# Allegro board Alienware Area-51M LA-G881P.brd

Outline 398.4 x 200.1 mm; copper layers: TOP, GND1, IN1, GND2, IN2, IN3, GND3, IN4, GND4, BOTTOM. Coordinates in mm from the lower left corner of the outline.

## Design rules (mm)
constraint set DEFAULT: min track width 0.112
net group 10: nets HDA_BIT_CLK_R MIC_CLK
net group CLK_PEG_0: nets CLK_PEG_N0 CLK_PEG_P0
net group CORE_V1: nets CORE_V1N CORE_V1P
net group CORE_V2: nets CORE_V2N CORE_V2P
net group CORE_V3: nets CORE_V3N CORE_V3P
net group CORE_V4: nets CORE_V4N CORE_V4P
net group CORE_V5: nets CORE_V5N CORE_V5P
net group CORE_V6: nets CORE_V6N CORE_V6P
net group CPU-SIGNAL: nets EC_PECI H_PM_SYNC
net group CSI_CHG: nets CSIN_CHG CSIP_CHG
net group CSI_ISL95338_1: nets CSIN_ISL95338_1 CSIP_ISL95338_1
net group CSI_ISL95338_2: nets CSIN_ISL95338_2 CSIP_ISL95338_2
net group CSO_CHG: nets CSON_CHG CSOP_CHG
net group CSS_1: nets CSSN_1 CSSP_1
net group CSS_2: nets CSSN_2 CSSP_2
net group DDR_B_CLK2: nets DDR_B_CLK2 DDR_B_CLK#2
net group DDR_B_CLK3: nets DDR_B_CLK3 DDR_B_CLK#3
net group DIFFPAIR22: nets TP_CLK_R TP_DATA_R
net group DIFFPAIR23: nets TP_CLK TP_DATA
net group DIFFPAIR40: nets PCIE_CTX_TRX_N24 PCIE_CTX_TRX_P24
net group DIFFPAIR41: nets PCIE_CTX_TRX_N23 PCIE_CTX_TRX_P23
net group DIFFPAIR42: nets PCIE_CTX_TRX_N22 PCIE_CTX_TRX_P22
net group DIFFPAIR43: nets PCIE_CTX_TRX_N21 PCIE_CTX_TRX_P21
net group DIFFPAIR44: nets PCIE_CRX_TTX_N24 PCIE_CRX_TTX_P24
net group DIFFPAIR45: nets PCIE_CRX_TTX_N23 PCIE_CRX_TTX_P23
net group DIFFPAIR46: nets PCIE_CRX_TTX_N22 PCIE_CRX_TTX_P22
net group DIFFPAIR47: nets PCIE_CRX_TTX_N21 PCIE_CRX_TTX_P21
net group DIFFPAIR48: nets USB20_N10_R USB20_P10_R
net group GT_V1: nets GT_V1N GT_V1P
net group GT_V2: nets GT_V2N GT_V2P
net group ISEN1_CHG: nets ISEN1N_CHG ISEN1P_CHG
net group ISUM_GT: nets ISUMN_GT ISUMP_GT
net group ISUM_VCORE: nets ISUMN_VCORE ISUMP_VCORE
net group PCH_SMB: nets PCH_SMBCLK PCH_SMBDATA
net group PCH_XDP_CLK_: nets PCH_XDP_CLK_N PCH_XDP_CLK_P
net group PCIE_CTX_C_RD_TRX_24: nets PCIE_CTX_C_RD_TRX_N24 PCIE_CTX_C_RD_TRX_P24
net group PCIE_CTX_C_TRX_22: nets PCIE_CTX_C_TRX_N22 PCIE_CTX_C_TRX_P22
net group PCIE_CTX_C_TRX_23: nets PCIE_CTX_C_TRX_N23 PCIE_CTX_C_TRX_P23
net group PCIE_CTX_C_TRX_24: nets PCIE_CTX_C_TRX_N24 PCIE_CTX_C_TRX_P24
net group PCIE_RCOMP: nets PCIE_RCOMPN PCIE_RCOMPP
net group REMOTE1: nets REMOTE1+ REMOTE1-
net group REMOTE2: nets REMOTE2+ REMOTE2-
net group REMOTE3: nets REMOTE3+ REMOTE3-
net group REMOTE4: nets REMOTE4+ REMOTE4-
net group SENSE: nets VCCIO_SENSE VCCSA_SENSE
net group TBTA_DIG_AUD_: nets TBTA_DIG_AUD_N TBTA_DIG_AUD_P
net group UART: nets UART_2_PRXD_DTXD UART_2_PTXD_DRXD
net group VCCSA_SENSE: nets VCCSA_SENSEN VCCSA_SENSEP
net group 85H_PCIE: nets CNV_PRX_DTX_N0
net group ASYNCHRONOUS: nets CALDERA_RST# CDRA_RST# CPU_TRIGGER DGPU_HOLD_RST# DGPU_PWROK EDP_RCOMP H_CPUPWRGD H_DRAMRST# H_PECI H_PM_DOWN H_PM_SYNC_R H_PROCHOT# H_PROCHOT#_R H_THERMTRIP# H_THERMTRIP#_R H_VCCST_PWRGD PCH_DPWROK PCH_PLTRST# PCH_PWROK PCH_TRIGGER PEG_RCOMP SYS_PWROK TBT_RST#_R USB2_COMP VR_SVID_CLK
net group AUDIO: nets HDA_BIT_CLK HDA_RST# HDA_SDIN HDA_SDOUT HDA_SDOUT_R HDA_SYNC HDA_SYNC_R
net group CNV_PRX_DTX_0_R: nets CNV_PRX_DTX_N0_R
net group CRYSTAL: nets PCH_RTCX1 PCH_RTCX2 TBT_XTAL_25_IN TBT_XTAL_25_OUT XTAL24_IN XTAL24_IN_R XTAL24_OUT XTAL24_OUT_R
net group DDI: nets CPU_DP1_AUXN CPU_DP1_AUXN_C CPU_DP1_AUXP CPU_DP1_AUXP_C CPU_DP1_HPD CPU_DP1_N0 CPU_DP1_N0_C CPU_DP1_N1 CPU_DP1_N1_C CPU_DP1_N2 CPU_DP1_N2_C CPU_DP1_N3 CPU_DP1_N3_C CPU_DP1_P0 CPU_DP1_P0_C CPU_DP1_P1 CPU_DP1_P1_C CPU_DP1_P2 CPU_DP1_P2_C CPU_DP1_P3 CPU_DP1_P3_C CPU_DP2_AUXN CPU_DP2_AUXN_C CPU_DP2_AUXP CPU_DP2_AUXP_C CPU_DP2_HPD CPU_DP2_N0 CPU_DP2_N0_C CPU_DP2_N1 CPU_DP2_N1_C CPU_DP2_N2 CPU_DP2_N2_C CPU_DP2_N3 CPU_DP2_N3_C CPU_DP2_P0 CPU_DP2_P0_C CPU_DP2_P1 CPU_DP2_P1_C CPU_DP2_P2 CPU_DP2_P2_C CPU_DP2_P3 CPU_DP2_P3_C
net group DDRA-ADD: nets DDR_A_ACT# DDR_A_BA0 DDR_A_BA1 DDR_A_BG0 DDR_A_BG1 DDR_A_CAS# DDR_A_MA0 DDR_A_MA1 DDR_A_MA2 DDR_A_MA3 DDR_A_MA4 DDR_A_MA5 DDR_A_MA6 DDR_A_MA7 DDR_A_MA8 DDR_A_MA9 DDR_A_MA10 DDR_A_MA11 DDR_A_MA12 DDR_A_MA13 DDR_A_PAR DDR_A_RAS# DDR_A_WE#
net group DDRA-CLK: nets DDR_A_CLK0 DDR_A_CLK1 DDR_A_CLK2 DDR_A_CLK3 DDR_A_CLK#0 DDR_A_CLK#1 DDR_A_CLK#2 DDR_A_CLK#3
net group DDRA-CTL: nets DDR_A_CKE0 DDR_A_CKE1 DDR_A_CKE2 DDR_A_CKE3 DDR_A_CS#0 DDR_A_CS#1 DDR_A_CS#2 DDR_A_CS#3 DDR_A_ODT0 DDR_A_ODT1 DDR_A_ODT2 DDR_A_ODT3
net group DDRA-D0: nets DDR_A_D0 DDR_A_D1 DDR_A_D2 DDR_A_D3 DDR_A_D4 DDR_A_D5 DDR_A_D6 DDR_A_D7
net group DDRA-D1: nets DDR_A_D8 DDR_A_D9 DDR_A_D10 DDR_A_D11 DDR_A_D12 DDR_A_D13 DDR_A_D14 DDR_A_D15
net group DDRA-D2: nets DDR_A_D16 DDR_A_D17 DDR_A_D18 DDR_A_D19 DDR_A_D20 DDR_A_D21 DDR_A_D22 DDR_A_D23
net group DDRA-D3: nets DDR_A_D24 DDR_A_D25 DDR_A_D26 DDR_A_D27 DDR_A_D28 DDR_A_D29 DDR_A_D30 DDR_A_D31
net group DDRA-D4: nets DDR_A_D32 DDR_A_D33 DDR_A_D34 DDR_A_D35 DDR_A_D36 DDR_A_D37 DDR_A_D38 DDR_A_D39
net group DDRA-D5: nets DDR_A_D40 DDR_A_D41 DDR_A_D42 DDR_A_D43 DDR_A_D44 DDR_A_D45 DDR_A_D46 DDR_A_D47
net group DDRA-D6: nets DDR_A_D48 DDR_A_D49 DDR_A_D50 DDR_A_D51 DDR_A_D52 DDR_A_D53 DDR_A_D54 DDR_A_D55
net group DDRA-D7: nets DDR_A_D56 DDR_A_D57 DDR_A_D58 DDR_A_D59 DDR_A_D60 DDR_A_D61 DDR_A_D62 DDR_A_D63
net group DDRA-DQS: nets DDR_A_DQS0 DDR_A_DQS1 DDR_A_DQS2 DDR_A_DQS3 DDR_A_DQS4 DDR_A_DQS5 DDR_A_DQS6 DDR_A_DQS7 DDR_A_DQS#0 DDR_A_DQS#1 DDR_A_DQS#2 DDR_A_DQS#3 DDR_A_DQS#4 DDR_A_DQS#5 DDR_A_DQS#6 DDR_A_DQS#7
net group DDRA-MA: nets DDR_A_ALERT#
net group DDRA-RESET: nets DDR_A_DRAMRST#
net group DDRB-ADD: nets DDR_B_ACT# DDR_B_BA0 DDR_B_BA1 DDR_B_BG0 DDR_B_BG1 DDR_B_CAS# DDR_B_MA0 DDR_B_MA1 DDR_B_MA2 DDR_B_MA3 DDR_B_MA4 DDR_B_MA5 DDR_B_MA6 DDR_B_MA7 DDR_B_MA8 DDR_B_MA9 DDR_B_MA10 DDR_B_MA11 DDR_B_MA12 DDR_B_MA13 DDR_B_PAR DDR_B_RAS# DDR_B_WE#
net group DDRB-CLK: nets DDR_B_CLK0 DDR_B_CLK1 DDR_B_CLK#0 DDR_B_CLK#1
net group DDRB-CTL: nets DDR_B_CKE0 DDR_B_CKE1 DDR_B_CKE2 DDR_B_CKE3 DDR_B_CS#0 DDR_B_CS#1 DDR_B_CS#2 DDR_B_CS#3 DDR_B_ODT0 DDR_B_ODT1 DDR_B_ODT2 DDR_B_ODT3
net group DDRB-D0: nets DDR_B_D0 DDR_B_D1 DDR_B_D2 DDR_B_D3 DDR_B_D4 DDR_B_D5 DDR_B_D6 DDR_B_D7
net group DDRB-D1: nets DDR_B_D8 DDR_B_D9 DDR_B_D10 DDR_B_D11 DDR_B_D12 DDR_B_D13 DDR_B_D14 DDR_B_D15
net group DDRB-D2: nets DDR_B_D16 DDR_B_D17 DDR_B_D18 DDR_B_D19 DDR_B_D20 DDR_B_D21 DDR_B_D22 DDR_B_D23
net group DDRB-D3: nets DDR_B_D24 DDR_B_D25 DDR_B_D26 DDR_B_D27 DDR_B_D28 DDR_B_D29 DDR_B_D30 DDR_B_D31
net group DDRB-D4: nets DDR_B_D32 DDR_B_D33 DDR_B_D34 DDR_B_D35 DDR_B_D36 DDR_B_D37 DDR_B_D38 DDR_B_D39
net group DDRB-D5: nets DDR_B_D40 DDR_B_D41 DDR_B_D42 DDR_B_D43 DDR_B_D44 DDR_B_D45 DDR_B_D46 DDR_B_D47
net group DDRB-D6: nets DDR_B_D48 DDR_B_D49 DDR_B_D50 DDR_B_D51 DDR_B_D52 DDR_B_D53 DDR_B_D54 DDR_B_D55
net group DDRB-D7: nets DDR_B_D56 DDR_B_D57 DDR_B_D58 DDR_B_D59 DDR_B_D60 DDR_B_D61 DDR_B_D62 DDR_B_D63
net group DDRB-DQS: nets DDR_B_DQS0 DDR_B_DQS1 DDR_B_DQS2 DDR_B_DQS3 DDR_B_DQS4 DDR_B_DQS5 DDR_B_DQS6 DDR_B_DQS7 DDR_B_DQS#0 DDR_B_DQS#1 DDR_B_DQS#2 DDR_B_DQS#3 DDR_B_DQS#4 DDR_B_DQS#5 DDR_B_DQS#6 DDR_B_DQS#7
net group DDRB-MA: nets DDR_B_ALERT#
net group DDRB-RESET: nets DDR_B_DRAMRST#
net group DIFFPAIR2: nets DAT_SMB
net group DMI: nets DMI_CRX_PTX_N0 DMI_CRX_PTX_N1 DMI_CRX_PTX_N2 DMI_CRX_PTX_N3 DMI_CRX_PTX_P0 DMI_CRX_PTX_P1 DMI_CRX_PTX_P2 DMI_CRX_PTX_P3 DMI_CTX_PRX_N0 DMI_CTX_PRX_N1 DMI_CTX_PRX_N2 DMI_CTX_PRX_N3 DMI_CTX_PRX_P0 DMI_CTX_PRX_P1 DMI_CTX_PRX_P2 DMI_CTX_PRX_P3
net group EMI: nets BST1_R_ISL95338_1 BST1_R_ISL95338_2 BST2_3V BST2_5V BST2_+1VALWP BST2_R_ISL95338_1 BST2_R_ISL95338_2 BST2_VCCIO BST_1.2V BST_3V BST_5V BST_+1VALWP BST_CHG BST_CHG_R BST_VCCIO CKXTAL1 CKXTAL1_R CKXTAL2 CKXTAL2_R CLK_PCI_ESPI CLK_SMB CNV_BRI_PRX_DTX CNV_BRI_PRX_DTX_R CNV_BRI_PTX_DRX CNV_BRI_PTX_DRX_R CNV_WT_RCOMP CPU_DISPA_BCLK CPU_DISPA_BCLK_R DDR_VTT_CNTL DP_HPD_PCH EC_PECI_R EC_RX EC_TX HDA_SPKR HDMI_HPD_PCH LG1_ISL95338_1 LG1_ISL95338_2 LG2_ISL95338_1 LG2_ISL95338_2 LG_3V LG_5V LX2_ISL95338_1 LX_3V LX_5V LX_VCCIO OSC24M_IN OSC24M_IN_R OSC24M_OUT OSC24M_OUT_R PCH_DP3_CTRL_DATA REFCLK_CNV REFCLK_CNV_H REFCLK_CNV_R RJ45_CT RJ45_CT0 RJ45_CT1 RJ45_CT2 RJ45_CT3 SNB_3V SNB_5V SNB_VCCIO SPI_CLK_R SUSCLK TBT_EE_CLK_R TBT_TMU_CLK_OUT TBTA_HPD TBTA_LSRX TBTA_LSTX UG1_ISL95338_2 UG2_ISL95338_1 UG2_ISL95338_2 UG_3V UG_5V UG_CHG UG_CHG_R VR_SVID_CLK_R
net group I2C: nets I2C_0_SCL I2C_0_SCL_R I2C_0_SDA I2C_0_SDA_R ISH_I2C0_SCL ISH_I2C0_SDA ISH_I2C1_SCL ISH_I2C1_SCL_R ISH_I2C1_SDA ISH_I2C1_SDA_R TBT_I2C_SCL TBT_I2C_SDA
net group LAN: nets LAN_MDIN0 LAN_MDIN1 LAN_MDIN2 LAN_MDIN3 LAN_MDIP0 LAN_MDIP1 LAN_MDIP2 LAN_MDIP3 RJ45_MDIN0 RJ45_MDIN1 RJ45_MDIN2 RJ45_MDIN3 RJ45_MDIP0 RJ45_MDIP1 RJ45_MDIP2 RJ45_MDIP3
net group PCIE: nets CNV_PRX_DTX_N1 CNV_PRX_DTX_N1_R CNV_PRX_DTX_P0 CNV_PRX_DTX_P0_R CNV_PRX_DTX_P1 CNV_PRX_DTX_P1_R CNV_PTX_C_DRX_N0 CNV_PTX_C_DRX_N1 CNV_PTX_C_DRX_P0 CNV_PTX_C_DRX_P1 CNV_PTX_DRX_N0 CNV_PTX_DRX_N1 CNV_PTX_DRX_P0 CNV_PTX_DRX_P1 CNV_RGI_PRX_DTX CNV_RGI_PRX_DTX_R CNV_RGI_PTX_DRX CNV_RGI_PTX_DRX_R PCIE_CRX_C_RD_TTX_N21 PCIE_CRX_C_RD_TTX_N22 PCIE_CRX_C_RD_TTX_N23 PCIE_CRX_C_RD_TTX_N24 PCIE_CRX_C_RD_TTX_P21 PCIE_CRX_C_RD_TTX_P22 PCIE_CRX_C_RD_TTX_P23 PCIE_CRX_C_RD_TTX_P24 PCIE_CRX_C_TTX_N21 PCIE_CRX_C_TTX_N22 PCIE_CRX_C_TTX_N23 PCIE_CRX_C_TTX_N24 PCIE_CRX_C_TTX_P21 PCIE_CRX_C_TTX_P22 PCIE_CRX_C_TTX_P23 PCIE_CRX_C_TTX_P24 PCIE_CRX_RD_TTX_N21 PCIE_CRX_RD_TTX_N22 PCIE_CRX_RD_TTX_N23 PCIE_CRX_RD_TTX_N24 PCIE_CRX_RD_TTX_P21 PCIE_CRX_RD_TTX_P22 PCIE_CRX_RD_TTX_P23 PCIE_CRX_RD_TTX_P24 PCIE_CTX_C_RD_TRX_N21 PCIE_CTX_C_RD_TRX_N22 PCIE_CTX_C_RD_TRX_N23 PCIE_CTX_C_RD_TRX_P21 PCIE_CTX_C_RD_TRX_P22 PCIE_CTX_C_RD_TRX_P23 PCIE_CTX_C_TRX_N21 PCIE_CTX_C_TRX_P21 PCIE_CTX_RD_TRX_N21 PCIE_CTX_RD_TRX_N22 PCIE_CTX_RD_TRX_N23 PCIE_CTX_RD_TRX_N24 PCIE_CTX_RD_TRX_P21 PCIE_CTX_RD_TRX_P22 PCIE_CTX_RD_TRX_P23 PCIE_CTX_RD_TRX_P24 PCIE_PRX_C_DTX_N15 PCIE_PRX_C_DTX_P15 PCIE_PRX_DTX_N9 PCIE_PRX_DTX_N10 PCIE_PRX_DTX_N11 PCIE_PRX_DTX_N12 PCIE_PRX_DTX_N15 PCIE_PRX_DTX_N16 PCIE_PRX_DTX_N17 PCIE_PRX_DTX_N18 PCIE_PRX_DTX_N19 PCIE_PRX_DTX_N20 PCIE_PRX_DTX_P9 PCIE_PRX_DTX_P10 PCIE_PRX_DTX_P11 PCIE_PRX_DTX_P12 PCIE_PRX_DTX_P15 PCIE_PRX_DTX_P16 PCIE_PRX_DTX_P17 PCIE_PRX_DTX_P18 PCIE_PRX_DTX_P19 PCIE_PRX_DTX_P20 PCIE_PTX_C_DRX_N9 PCIE_PTX_C_DRX_N10 PCIE_PTX_C_DRX_N11 PCIE_PTX_C_DRX_N12 PCIE_PTX_C_DRX_N15 PCIE_PTX_C_DRX_N16 PCIE_PTX_C_DRX_N17 PCIE_PTX_C_DRX_N18 PCIE_PTX_C_DRX_N19 PCIE_PTX_C_DRX_N20 PCIE_PTX_C_DRX_P9 PCIE_PTX_C_DRX_P10 PCIE_PTX_C_DRX_P11 PCIE_PTX_C_DRX_P12 PCIE_PTX_C_DRX_P15 PCIE_PTX_C_DRX_P16 PCIE_PTX_C_DRX_P17 PCIE_PTX_C_DRX_P18 PCIE_PTX_C_DRX_P19 PCIE_PTX_C_DRX_P20 PCIE_PTX_DRX_N9 PCIE_PTX_DRX_N10 PCIE_PTX_DRX_N11 PCIE_PTX_DRX_N12 PCIE_PTX_DRX_N15 PCIE_PTX_DRX_N16 PCIE_PTX_DRX_N17 PCIE_PTX_DRX_N18 PCIE_PTX_DRX_N19 PCIE_PTX_DRX_N20 PCIE_PTX_DRX_P9 PCIE_PTX_DRX_P10 PCIE_PTX_DRX_P11 PCIE_PTX_DRX_P12 PCIE_PTX_DRX_P15 PCIE_PTX_DRX_P16 PCIE_PTX_DRX_P17 PCIE_PTX_DRX_P18 PCIE_PTX_DRX_P19 PCIE_PTX_DRX_P20
net group PEG: nets PEG_CRX_C_GTX_N0 PEG_CRX_C_GTX_N1 PEG_CRX_C_GTX_N2 PEG_CRX_C_GTX_N3 PEG_CRX_C_GTX_N4 PEG_CRX_C_GTX_N5 PEG_CRX_C_GTX_N6 PEG_CRX_C_GTX_N7 PEG_CRX_C_GTX_P0 PEG_CRX_C_GTX_P1 PEG_CRX_C_GTX_P2 PEG_CRX_C_GTX_P3 PEG_CRX_C_GTX_P4 PEG_CRX_C_GTX_P5 PEG_CRX_C_GTX_P6 PEG_CRX_C_GTX_P7 PEG_CRX_C_RD_GTX_N8 PEG_CRX_C_RD_GTX_N9 PEG_CRX_C_RD_GTX_N10 PEG_CRX_C_RD_GTX_N11 PEG_CRX_C_RD_GTX_P8 PEG_CRX_C_RD_GTX_P9 PEG_CRX_C_RD_GTX_P10 PEG_CRX_C_RD_GTX_P11 PEG_CRX_GTX_N0 PEG_CRX_GTX_N1 PEG_CRX_GTX_N2 PEG_CRX_GTX_N3 PEG_CRX_GTX_N4 PEG_CRX_GTX_N5 PEG_CRX_GTX_N6 PEG_CRX_GTX_N7 PEG_CRX_GTX_N8 PEG_CRX_GTX_N9 PEG_CRX_GTX_N10 PEG_CRX_GTX_N11 PEG_CRX_GTX_P0 PEG_CRX_GTX_P1 PEG_CRX_GTX_P2 PEG_CRX_GTX_P3 PEG_CRX_GTX_P4 PEG_CRX_GTX_P5 PEG_CRX_GTX_P6 PEG_CRX_GTX_P7 PEG_CRX_GTX_P8 PEG_CRX_GTX_P9 PEG_CRX_GTX_P10 PEG_CRX_GTX_P11 PEG_CRX_RD_GTX_N8 PEG_CRX_RD_GTX_N9 PEG_CRX_RD_GTX_N10 PEG_CRX_RD_GTX_N11 PEG_CRX_RD_GTX_P8 PEG_CRX_RD_GTX_P9 PEG_CRX_RD_GTX_P10 PEG_CRX_RD_GTX_P11 PEG_CTX_C_GRX_N0 PEG_CTX_C_GRX_N1 PEG_CTX_C_GRX_N2 PEG_CTX_C_GRX_N3 PEG_CTX_C_GRX_N4 PEG_CTX_C_GRX_N5 PEG_CTX_C_GRX_N6 PEG_CTX_C_GRX_N7 PEG_CTX_C_GRX_N8 PEG_CTX_C_GRX_N9 PEG_CTX_C_GRX_N10 PEG_CTX_C_GRX_N11 PEG_CTX_C_GRX_P0 PEG_CTX_C_GRX_P1 PEG_CTX_C_GRX_P2 PEG_CTX_C_GRX_P3 PEG_CTX_C_GRX_P4 PEG_CTX_C_GRX_P5 PEG_CTX_C_GRX_P6 PEG_CTX_C_GRX_P7 PEG_CTX_C_GRX_P8 PEG_CTX_C_GRX_P9 PEG_CTX_C_GRX_P10 PEG_CTX_C_GRX_P11 PEG_CTX_GRX_N0 PEG_CTX_GRX_N1 PEG_CTX_GRX_N2 PEG_CTX_GRX_N3 PEG_CTX_GRX_N4 PEG_CTX_GRX_N5 PEG_CTX_GRX_N6 PEG_CTX_GRX_N7 PEG_CTX_GRX_N8 PEG_CTX_GRX_N9 PEG_CTX_GRX_N10 PEG_CTX_GRX_N11 PEG_CTX_GRX_P0 PEG_CTX_GRX_P1 PEG_CTX_GRX_P2 PEG_CTX_GRX_P3 PEG_CTX_GRX_P4 PEG_CTX_GRX_P5 PEG_CTX_GRX_P6 PEG_CTX_GRX_P7 PEG_CTX_GRX_P8 PEG_CTX_GRX_P9 PEG_CTX_GRX_P10 PEG_CTX_GRX_P11
net group PLATFORM-CLK: nets CLK_CNV_PRX_DTX_N CLK_CNV_PRX_DTX_N_R CLK_CNV_PRX_DTX_P CLK_CNV_PRX_DTX_P_R CLK_CNV_PTX_DRX_N CLK_CNV_PTX_DRX_N_R CLK_CNV_PTX_DRX_P CLK_CNV_PTX_DRX_P_R CLK_PCIE_DGPU#_C CLK_PCIE_DGPU_C CLK_PCIE_N1 CLK_PCIE_N2 CLK_PCIE_N3 CLK_PCIE_N3_C CLK_PCIE_N4 CLK_PCIE_N5 CLK_PCIE_P1 CLK_PCIE_P2 CLK_PCIE_P3 CLK_PCIE_P3_C CLK_PCIE_P4 CLK_PCIE_P5 CLK_PEG_N6 CLK_PEG_P6 CPU_24MHZ_N CPU_24MHZ_P PCH_CPU_BCLK_N PCH_CPU_BCLK_P PCH_CPU_PCIBCLK_N PCH_CPU_PCIBCLK_P
net group SATA: nets SATA_PRX_C_DTX_N0 SATA_PRX_C_DTX_P0 SATA_PRX_DTX_N0 SATA_PRX_DTX_P0 SATA_PTX_C_DRX_N0 SATA_PTX_C_DRX_P0 SATA_PTX_DRX_N0 SATA_PTX_DRX_P0
net group SINGLE-NET_15: nets INTRUDER# PBTN_OUT# PCH_RTCRST# PCH_SRTCRST# PCIE_WAKE# WAKE#
net group SMB: nets CDRA_CLK CDRA_DAT CPU_DDC1CLK CPU_DDC1DATA CPU_DDC2CLK CPU_DDC2DATA CPU_DP1_CTRL_CLK CPU_DP1_CTRL_DATA CPU_DP2_CTRL_CLK CPU_DP2_CTRL_DATA EC_CLK1 EC_DAT1 EC_ESB_CLK EC_ESB_DAT EC_SMB_CK1 EC_SMB_CK2 EC_SMB_DA1 EC_SMB_DA2 I2C0_SCL_EC I2C0_SDA_EC I2C_CLK I2C_DAT SML0CLK SML0DATA SML1CLK SML1DATA TBTA_I2C_SCL1_R TBTA_I2C_SDA1_R
net group SPI: nets PCH_SPI_0_CLK PCH_SPI_0_CLK_R PCH_SPI_0_CS# PCH_SPI_0_HOLD# PCH_SPI_0_SI PCH_SPI_0_SI_R PCH_SPI_0_SO PCH_SPI_0_SO_R PCH_SPI_0_WP# PCH_SPI_0_WP#_R PD_EE_CLK PD_EE_CS_N PD_EE_DI PD_EE_DO SPI_CLK SPI_CS# SPI_MOSI TBT_EE_CLK TBT_EE_CS_N TBT_EE_DI TBT_EE_DO TBT_EE_WP_N
net group SPI_8: nets PCH_SPI_0_HOLD#_R
net group TBT: nets TBT_A_AUX_N TBT_A_AUX_N_C TBT_A_AUX_P TBT_A_AUX_P_C TBT_A_TRX_DTX_N0 TBT_A_TRX_DTX_N1 TBT_A_TRX_DTX_P0 TBT_A_TRX_DTX_P1 TBT_A_TTX_C_DRX_N0 TBT_A_TTX_C_DRX_N1 TBT_A_TTX_C_DRX_P0 TBT_A_TTX_C_DRX_P1 TBT_A_TTX_DRX_N0 TBT_A_TTX_DRX_N1 TBT_A_TTX_DRX_P0 TBT_A_TTX_DRX_P1 TBT_A_USB20_L_NB TBT_A_USB20_L_NT TBT_A_USB20_L_PB TBT_A_USB20_L_PT TBT_A_USB20_N TBT_A_USB20_NB TBT_A_USB20_NT TBT_A_USB20_P TBT_A_USB20_PB TBT_A_USB20_PT
net group USB20: nets CHR_USB20_N1 CHR_USB20_N1_R CHR_USB20_P1 CHR_USB20_P1_R USB20_N1 USB20_N2 USB20_N2_R USB20_N3 USB20_N3_R USB20_N4 USB20_N6 USB20_N7 USB20_N8 USB20_N8_R USB20_N9 USB20_N9_R USB20_N10 USB20_N11 USB20_N11_R USB20_N14 USB20_P1 USB20_P2 USB20_P2_R USB20_P3 USB20_P3_R USB20_P4 USB20_P6 USB20_P7 USB20_P8 USB20_P8_R USB20_P9 USB20_P9_R USB20_P10 USB20_P11 USB20_P11_R USB20_P14
net group USB30: nets USB3_PRX_C_DTX_N8 USB3_PRX_C_DTX_P8 USB3_PRX_C_RD_DTX_N6 USB3_PRX_C_RD_DTX_P6 USB3_PRX_DTX_N5 USB3_PRX_DTX_N6 USB3_PRX_DTX_N7 USB3_PRX_DTX_N8 USB3_PRX_DTX_P5 USB3_PRX_DTX_P6 USB3_PRX_DTX_P7 USB3_PRX_DTX_P8 USB3_PRX_RD_DTX_N6 USB3_PRX_RD_DTX_P6 USB3_PTX_C_DRX_N5 USB3_PTX_C_DRX_N6 USB3_PTX_C_DRX_N7 USB3_PTX_C_DRX_P5 USB3_PTX_C_DRX_P6 USB3_PTX_C_DRX_P7 USB3_PTX_C_RD_DRX_N6 USB3_PTX_C_RD_DRX_P6 USB3_PTX_DRX_N5 USB3_PTX_DRX_N6 USB3_PTX_DRX_N7 USB3_PTX_DRX_N8 USB3_PTX_DRX_P5 USB3_PTX_DRX_P6 USB3_PTX_DRX_P7 USB3_PTX_DRX_P8 USB3_PTX_RD_DRX_N6 USB3_PTX_RD_DRX_P6
net group XDP: nets CFG0 CFG2 CFG3 CFG4 CFG5 CFG6 CFG7 CFG8 CFG9 CFG10 CFG11 CFG12 CFG13 CFG14 CFG15 CFG16 CFG17 CFG18 CFG19 CPU_XDP_TRST#
nets with their own width: min track width 0.254; nets +1.2V_VCCPLL_OC +1.05V_VCCST +1VALWP +3.3V_TBT_SX +3VALW_PD +3VS_ACC +5VS_TP_LED +VDD09 +VDD18 +VDD25
nets with their own width: min track width 0.508; nets +0.6V_DDR_REFCA_A +0.6V_DDR_REFCA_B +0.6V_VREF_CA +0.6V_VREF_DQ +0.6VSP +0.9V_CIO +0.9V_DP +0.9V_LVR_OUT +0.9V_PCIE +0.9V_SVR +0.9V_USB +1.2VP +1.8V_PRIM +1.8VA_TBTA_LDO +1.8VALW +1.8VD_TBTA_LDO +1.8VSP +1V_MPHY +1VALW +1VALWP_B+ +1VALWP_PGOOD +2.5V_MEMP +2.5VOUT +2.5VSP_ADJ +2.5VSP_ON +2.5VSP_PGOOD +2.5VSP_VIN +3.3V_ANA_PCIE +3.3V_ANA_USB2 +3.3V_FLASH +3.3V_LC +3.3V_TBT_SX_R +3VALW +3VALWP +3VLP +3VSP_SSD +5V_USB_PWR2 +5VALW +5VALW_LED +5VALWP +5VS +12V_COMP +12V_COMP_1 +12V_ENA +12V_FAN +12V_FB +12V_LX +12V_SNUB +12V_SS +12V_VIN +12VP +19V_ADPIN_1 +19V_ADPIN_2 +19V_VIN_1 +19V_VIN_2 +AVDD09 +AVDD18 +AVDD25 +AVDD33 +DVDD09 +DVDD18 +DVDD18_UPS +DVDD25_UPS +DVDD33 +DVDD3318 +EC_VCCA +EVDD09 +EVDD18 +PWR_SRC +RTC_CELL +SDC_IN +V18R +VCC_CORE +VCCGT +VCCIO +VCCIOP +VCCRTCEXT +VCCSA +VCCST_PECI +VDDA GND
nets with their own width: min track width 0.635; nets +3.3V_ELC
nets with their own width: min track width 1.016; nets +2.5V_MEM +3VS
nets with their own width: min track width 1.524; nets +3V_WLAN +5V_HDD +LCDVDD
nets with their own width: min track width 2.032; nets +3V_PCH +5V_TOBII
nets with their own width: min track width 3.048; nets +0.6VS +TBTA_VBUS
nets with their own width: min track width 3.556; nets +1.2V_DDR +5V_USB_PWR1

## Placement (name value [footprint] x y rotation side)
C1  .1U_0402_16V7K  [C_0402]  290.68 94.41 90 top
C2  0.1U_0402_10V6K  [C_0402]  102.46 17.78 90 bottom
C3  2200P_0402_25V7K  [C_0402]  163.7 100.76 180 top
C4  1U_0201_6.3V6M  [C_0201]  78.57 21.83 180 top
C5  1U_0201_6.3V6M  [C_0201]  78.58 22.4 180 top
C6  0.1U_0402_10V7K  [C_0402]  83.82 20.9 0 top
C8  47U_0805_6.3V6M  [C_0805]  83.98 22.25 0 top
C11  2.2U_0402_6.3VX5R  [C_0402]  163.7 99.85 180 top
C29  .1U_0402_16V7K  [C_0402]  92.13 22.35 0 top
C256  10U_0402_6.3V6M  [C_0402]  339.7 27.9 180 top
C257  10U_0603_6.3V6M  [C_0603]  345.22 25.42 90 top
C258  0.1U_0402_16V7K  [C_0402]  338.14 22.67 180 top
C260  10U_0402_6.3V6M  [C_0402]  342.42 15.59 270 top
C261  10U_0603_6.3V6M  [C_0603]  343.53 15.58 270 top
C262  10U_0603_6.3V6M  [C_0603]  338.67 23.77 180 top
C263  0.1U_0402_10V7K  [C_0402]  338.18 24.85 180 top
C264  10U_0603_6.3V6M  [C_0603]  338.67 18.06 0 top
C265  0.1U_0402_10V7K  [C_0402]  339.22 16.91 0 top
C266  10U_0402_6.3V6M  [C_0402]  271.8 90.5 90 top
C267  10U_0603_6.3V6M  [C_0603]  272.95 90.57 90 top
C268  0.01U_0402_16V  [C_0402]  279.79 84.35 0 top
C269  10U_0603_6.3V6M  [C_0603]  279.87 85.56 0 top
C270  0.1U_0402_10V7K  [C_0402]  279.79 86.76 0 top
C617  33P_0402_50V8J  [C_0402]  356.98 10.92 180 top
C618  33P_0402_50V8J  [C_0402]  356.98 10.03 180 top
C620  33P_0402_50V8J  [C_0402]  369.26 12.33 90 top
C621  .047U_0402_16V7K  [C_0402]  357 9.12 180 top
C622  22U_0402_6.3V6M  [C_0402]  356.98 11.83 180 top
C623  .047U_0402_16V7K  [C_0402]  357.96 5.38 0 top
C624  22U_0402_6.3V6M  [C_0402]  386.74 12.34 90 top
C625  .047U_0402_16V7K  [C_0402]  370.18 12.33 90 top
C627  .047U_0402_16V7K  [C_0402]  371.09 12.33 90 top
C628  33P_0402_50V8J  [C_0402]  387.65 12.34 90 top
C631  150U_B2_6.3VM_R35M  [C_B2]  356.31 13.97 0 top
C635  22U_0402_6.3V6M  [C_0402]  358.72 23.37 0 top
C636  22U_0402_6.3V6M  [C_0402]  358.75 24.28 0 top
C637  22U_0402_6.3V6M  [C_0402]  382.6 12.39 90 top
C638  22U_0402_6.3V6M  [C_0402]  383.54 12.39 90 top
C641  150U_B2_6.3VM_R35M  [C_B2]  373.66 15.77 270 bottom
C2498  0.1U_0402_10V6K  [C_0402]  223.24 108.38 90 bottom
C2500  2200P_0402_25V7K  [C_0402]  117.82 81.54 90 bottom
C2501  1U_0201_6.3V6M  [C_0201]  92.15 19.71 0 top
C2502  2200P_0402_25V7K  [C_0402]  224.59 106.98 0 bottom
C2506  220P_0402_50V8J  [C_0402]  343.18 20.83 0 top
C2507  470P_0402_50V7K  [C_0402]  343.15 21.74 0 top
C2508  1U_0201_6.3V6M  [C_0201]  92.15 20.28 0 top
C2509  0.1U_0402_25V6K~D  [C_0402]  86.79 19.99 180 top
C2510  2200P_0402_25V7K  [C_0402]  223.27 103.96 180 bottom
C2511  2200P_0402_25V7K  [C_0402]  370.08 18.97 0 bottom
C2512  10U_0603_6.3V6M  [C_0603]  363.84 11.89 0 top
C2513  47U_0603_6.3V6M  [C_0603]  363.87 13.1 0 top
C2514  10U_0603_6.3V6M  [C_0603]  363.7 16.56 0 top
C2515  10U_0603_6.3V6M  [C_0603]  363.67 15.31 0 top
C2516  0.1U_0402_10V7K  [C_0402]  359.95 18.06 90 top
C2518  0.1U_0402_10V7K  [C_0402]  168.81 99.79 0 top
C2519  0.1U_0402_10V7K  [C_0402]  168.78 101.5 0 top
C2521  0.1U_0402_10V7K  [C_0402]  78.84 21.05 180 top
C2522  0.1U_0402_10V7K  [C_0402]  276.69 87.97 0 top
C2523  0.1U_0402_10V7K  [C_0402]  343.15 22.65 0 top
C2524  0.1U_0402_10V7K  [C_0402]  343.15 19.89 0 top
C2525  0.1U_0402_10V7K  [C_0402]  339.24 19.23 0 top
C2531  0.1U_0402_10V6K  [C_0402]  113.82 7.01 180 bottom
C2532  2200P_0402_25V7K  [C_0402]  17.97 13.23 0 bottom
C2533  2200P_0402_25V7K  [C_0402]  113.64 7.9 90 bottom
C5360  .1U_0402_16V7K  [C_0402]  290.68 94.41 90 bottom
C5361  2200P_0402_25V7K  [C_0402]  221.49 103.99 180 bottom
CC1  100P_0402_50V8J  [C_0402]  120.59 85.86 180 top
CC2  5P_0402_50V8C  [C_0402]  122.66 86.79 90 bottom
CC3  100P_0402_50V8J  [C_0402]  120.2 84.03 180 top
CC4  100P_0402_50V8J  [C_0402]  120.2 83.12 180 top
CC6  0.22U_0402_6.3V7K  [C_0402]  138.81 103.96 90 bottom
CC7  0.22U_0402_6.3V7K  [C_0402]  137.9 103.93 90 bottom
CC8  0.22U_0402_6.3V7K  [C_0402]  136.04 103.96 90 bottom
CC9  0.22U_0402_6.3V7K  [C_0402]  136.96 103.96 90 bottom
CC10  0.22U_0402_6.3V7K  [C_0402]  135.13 103.96 90 bottom
CC11  0.22U_0402_6.3V7K  [C_0402]  134.21 103.96 90 bottom
CC12  0.22U_0402_6.3V7K  [C_0402]  133.3 103.96 90 bottom
CC13  0.22U_0402_6.3V7K  [C_0402]  132.38 103.96 90 bottom
CC14  0.22U_0402_6.3V7K  [C_0402]  131.47 103.96 90 bottom
CC15  0.22U_0402_6.3V7K  [C_0402]  130.56 103.96 90 bottom
CC16  0.22U_0402_6.3V7K  [C_0402]  129.64 103.96 90 bottom
CC17  0.22U_0402_6.3V7K  [C_0402]  128.73 103.96 90 bottom
CC18  0.22U_0402_6.3V7K  [C_0402]  127.81 103.96 90 bottom
CC19  0.22U_0402_6.3V7K  [C_0402]  126.9 103.96 90 bottom
CC20  0.22U_0402_6.3V7K  [C_0402]  125.98 103.96 90 bottom
CC21  0.22U_0402_6.3V7K  [C_0402]  125.07 103.96 90 bottom
CC22  22U_0603_6.3V6M  [C_0603]  176.03 58.29 180 top
CC23  22U_0603_6.3V6M  [C_0603]  176.69 64.36 180 top
CC24  22U_0603_6.3V6M  [C_0603]  175.26 66.95 180 top
CC25  22U_0603_6.3V6M  [C_0603]  175.26 54.79 180 top
CC26  22U_0603_6.3V6M  [C_0603]  137.44 101.24 180 top
CC27  22U_0603_6.3V6M  [C_0603]  145.19 73.49 180 top
CC28  22U_0603_6.3V6M  [C_0603]  150.27 74.19 0 top
CC29  22U_0603_6.3V6M  [C_0603]  150.27 75.4 0 top
CC30  22U_0603_6.3V6M  [C_0603]  149.43 104.07 90 bottom
CC31  1U_0201_6.3V6M  [C_0201]  148.32 103.88 180 bottom
CC32  22U_0805_6.3V6M~D  [C_0805]  152.53 72.35 270 top
CC33  22U_0603_6.3V6M  [C_0603]  144.04 72.38 270 top
CC34  22U_0603_6.3V6M  [C_0603]  145.26 72.4 270 top
CC35  22U_0603_6.3V6M  [C_0603]  148.49 71.99 270 top
CC36  22U_0603_6.3V6M  [C_0603]  149.76 72.02 270 top
CC37  22U_0603_6.3V6M  [C_0603]  151 72.02 270 top
CC38  22U_0603_6.3V6M  [C_0603]  150.65 104.07 90 bottom
CC46  1U_0201_6.3V6M  [C_0201]  153.76 74.8 0 top
CC47  22U_0603_6.3V6M  [C_0603]  137.44 99.97 180 top
CC48  22U_0603_6.3V6M  [C_0603]  137.44 102.51 180 top
CC49  47U_0805_6.3V6M  [C_0805]  132.72 100.23 0 top
CC50  47U_0805_6.3V6M  [C_0805]  129.8 100.23 0 top
CC51  47U_0805_6.3V6M  [C_0805]  132.72 102 0 top
CC52  47U_0805_6.3V6M  [C_0805]  129.8 102 0 top
CC56  0.22U_0201_6.3V  [C_0201]  122.67 96.49 180 bottom
CC57  0.22U_0201_6.3V  [C_0201]  122.67 98.25 180 bottom
CC58  0.22U_0201_6.3V  [C_0201]  122.67 94.74 180 bottom
CC59  0.22U_0201_6.3V  [C_0201]  122.67 97.08 180 bottom
CC60  0.22U_0201_6.3V  [C_0201]  122.67 97.66 180 bottom
CC61  0.22U_0201_6.3V  [C_0201]  122.67 95.91 180 bottom
CC62  0.22U_0201_6.3V  [C_0201]  122.67 95.32 180 bottom
CC63  0.22U_0201_6.3V  [C_0201]  122.67 94.16 180 bottom
CD1  10U_0603_6.3V6M  [C_0603]  244.87 65.68 0 top
CD2  10U_0603_6.3V6M  [C_0603]  255.74 61.16 0 top
CD3  10U_0603_6.3V6M  [C_0603]  244.72 61.87 0 top
CD4  10U_0603_6.3V6M  [C_0603]  244.77 68.37 0 top
CD5  10U_0603_6.3V6M  [C_0603]  255.82 57.53 0 top
CD6  10U_0603_6.3V6M  [C_0603]  269.7 77.3 270 top
CD7  10U_0603_6.3V6M  [C_0603]  244.97 55.47 0 top
CD8  10U_0603_6.3V6M  [C_0603]  244.8 58.14 0 top
CD9  1U_0201_6.3V6M  [C_0201]  255.64 72.97 0 top
CD10  1U_0201_6.3V6M  [C_0201]  253.28 49.78 0 top
CD11  1U_0201_6.3V6M  [C_0201]  245.81 90.75 180 top
CD12  1U_0201_6.3V6M  [C_0201]  243.12 75.87 0 top
CD13  1U_0201_6.3V6M  [C_0201]  243.22 44.98 0 top
CD14  1U_0201_6.3V6M  [C_0201]  253 40.16 0 top
CD15  1U_0201_6.3V6M  [C_0201]  247.56 34.97 0 top
CD16  1U_0201_6.3V6M  [C_0201]  255.71 29.51 0 top
CD17  330U_D2_2VM_R6M  [C_D2]  216.97 105.71 0 top
CD18  0.1U_0402_16V7K  [C_0402]  252.65 70.69 90 top
CD19  2.2U_0402_6.3V6M  [C_0402]  253.57 71.6 270 top
CD20  10U_0603_6.3V6M  [C_0603]  253.21 93.38 90 top
CD21  1U_0201_6.3V6M  [C_0201]  254.71 93.15 90 top
CD22  .1U_0402_16V7K  [C_0402]  243.61 94.84 180 top
CD23  2.2U_0402_6.3V6M  [C_0402]  242.7 93.93 0 top
CD24  10U_0603_6.3V6M  [C_0603]  251.97 93.38 90 top
CD25  10U_0603_6.3V6M  [C_0603]  245.29 94.02 90 top
CD27  1U_0201_6.3V6M  [C_0201]  244.4 93.86 90 top
CD28  1U_0201_6.3V6M  [C_0201]  254.13 93.15 90 top
CD29  .1U_0402_16V7K  [C_0402]  253.54 67.26 270 top
CD30  .1U_0402_16V7K  [C_0402]  252.65 69.8 0 top
CD31  0.022U_0402_25V7K  [C_0402]  255.65 67.41 0 top
CD32  10U_0603_6.3V6M  [C_0603]  230.8 68.65 0 top
CD33  10U_0603_6.3V6M  [C_0603]  240.19 65.17 180 top
CD34  10U_0603_6.3V6M  [C_0603]  240.78 54.46 180 top
CD35  10U_0603_6.3V6M  [C_0603]  240.12 57.48 180 top
CD36  10U_0603_6.3V6M  [C_0603]  231.2 60.22 0 top
CD37  10U_0603_6.3V6M  [C_0603]  240.02 60.45 180 top
CD38  10U_0603_6.3V6M  [C_0603]  230.8 55.22 0 top
CD39  10U_0603_6.3V6M  [C_0603]  240.3 50.29 180 top
CD40  1U_0201_6.3V6M  [C_0201]  241.54 31.16 180 top
CD41  1U_0201_6.3V6M  [C_0201]  229.81 36.22 0 top
CD42  1U_0201_6.3V6M  [C_0201]  239.05 39.49 0 top
CD43  1U_0201_6.3V6M  [C_0201]  234.02 45.64 0 top
CD44  1U_0201_6.3V6M  [C_0201]  237.12 82.83 0 top
CD45  1U_0201_6.3V6M  [C_0201]  229.42 89.61 0 top
CD46  1U_0201_6.3V6M  [C_0201]  242.33 74.32 180 top
CD47  1U_0201_6.3V6M  [C_0201]  229.3 78.43 180 top
CD48  330U_D2_2VM_R6M  [C_D2]  248.96 22.48 180 top
CD49  10U_0603_6.3V6M  [C_0603]  238.02 95.64 90 top
CD50  1U_0201_6.3V6M  [C_0201]  237.03 95.62 90 top
CD51  .1U_0402_16V7K  [C_0402]  237.34 71.24 270 top
CD52  2.2U_0402_6.3V6M  [C_0402]  236.42 71.24 270 top
CD53  10U_0603_6.3V6M  [C_0603]  239.27 95.64 90 top
CD54  .1U_0402_16V7K  [C_0402]  230 95.45 0 top
CD55  2.2U_0402_6.3V6M  [C_0402]  230.91 96.37 180 top
CD56  10U_0603_6.3V6M  [C_0603]  232.87 95.03 90 top
CD58  1U_0201_6.3V6M  [C_0201]  236.42 95.62 90 top
CD59  1U_0201_6.3V6M  [C_0201]  231.95 95.31 90 top
CD64  10U_0603_6.3V6M  [C_0603]  217.89 65.15 0 top
CD65  10U_0603_6.3V6M  [C_0603]  226.4 67.92 0 top
CD66  10U_0603_6.3V6M  [C_0603]  218.22 58.29 0 top
CD67  10U_0603_6.3V6M  [C_0603]  217.77 67.65 0 top
CD68  10U_0603_6.3V6M  [C_0603]  224.31 58.63 0 top
CD69  10U_0603_6.3V6M  [C_0603]  227.47 65.23 180 top
CD70  10U_0603_6.3V6M  [C_0603]  218.3 54.79 0 top
CD71  10U_0603_6.3V6M  [C_0603]  227.6 55.14 180 top
CD72  1U_0201_6.3V6M  [C_0201]  225.82 29.56 0 top
CD73  1U_0201_6.3V6M  [C_0201]  216.78 36.02 0 top
CD74  1U_0201_6.3V6M  [C_0201]  215.76 87.4 0 top
CD75  1U_0201_6.3V6M  [C_0201]  229.5 74.5 0 top
CD76  1U_0201_6.3V6M  [C_0201]  224.8 40.59 180 top
CD77  1U_0201_6.3V6M  [C_0201]  216.8 44.85 0 top
CD78  1U_0201_6.3V6M  [C_0201]  216.01 79.12 0 top
CD79  1U_0201_6.3V6M  [C_0201]  227.57 83.97 180 top
CD80  330U_D2_2VM_R6M  [C_D2]  233.4 105.71 180 top
CD81  .1U_0402_16V7K  [C_0402]  224.13 70.94 90 top
CD82  2.2U_0402_6.3V6M  [C_0402]  223.24 71.88 270 top
CD83  10U_0603_6.3V6M  [C_0603]  227.29 95.05 90 top
CD84  1U_0201_6.3V6M  [C_0201]  228.31 95.6 0 top
CD85  .1U_0402_16V7K  [C_0402]  217.86 95.73 180 top
CD86  2.2U_0402_6.3V6M  [C_0402]  216.94 94.79 0 top
CD87  10U_0603_6.3V6M  [C_0603]  226.07 95.05 90 top
CD88  10U_0603_6.3V6M  [C_0603]  219.56 94.09 90 top
CD89  1U_0201_6.3V6M  [C_0201]  218.59 94.65 90 top
CD90  1U_0201_6.3V6M  [C_0201]  228.31 95.02 0 top
CD94  10U_0603_6.3V6M  [C_0603]  200.9 70.91 0 top
CD95  10U_0603_6.3V6M  [C_0603]  205.54 60.06 270 top
CD96  10U_0603_6.3V6M  [C_0603]  213.6 67.66 180 top
CD97  10U_0603_6.3V6M  [C_0603]  213.37 61.24 180 top
CD98  10U_0603_6.3V6M  [C_0603]  213.58 58.04 180 top
CD99  10U_0603_6.3V6M  [C_0603]  212.89 54.99 180 top
CD100  10U_0603_6.3V6M  [C_0603]  203.87 56.34 0 top
CD101  10U_0603_6.3V6M  [C_0603]  203.92 66.98 0 top
CD102  1U_0201_6.3V6M  [C_0201]  215.94 31.49 180 top
CD103  1U_0201_6.3V6M  [C_0201]  202.37 46.1 0 top
CD104  1U_0201_6.3V6M  [C_0201]  214.85 38.43 180 top
CD105  1U_0201_6.3V6M  [C_0201]  203.59 34.29 0 top
CD106  1U_0201_6.3V6M  [C_0201]  201.74 89.3 180 top
CD107  1U_0201_6.3V6M  [C_0201]  214.67 82.67 180 top
CD108  1U_0201_6.3V6M  [C_0201]  202.68 78.31 0 top
CD109  1U_0201_6.3V6M  [C_0201]  214.24 73.24 0 top
CD110  330U_D2_2VM_R6M  [C_D2]  237.51 22.5 180 top
CD111  10U_0603_6.3V6M  [C_0603]  214.02 94.22 90 top
CD112  1U_0201_6.3V6M  [C_0201]  211.2 95.24 90 top
CD113  .1U_0402_16V7K  [C_0402]  212.39 71.24 270 top
CD114  2.2U_0402_6.3V6M  [C_0402]  213.33 71.24 270 top
CD115  10U_0603_6.3V6M  [C_0603]  212.75 94.19 90 top
CD116  .1U_0402_16V7K  [C_0402]  202.64 91.82 0 top
CD117  2.2U_0402_6.3V6M  [C_0402]  203.58 92.73 180 top
CD118  10U_0603_6.3V6M  [C_0603]  204.98 93.18 90 top
CD119  1U_0201_6.3V6M  [C_0201]  211.78 95.24 90 top
CD120  1U_0201_6.3V6M  [C_0201]  205.94 94.02 90 top
CD125  0.1U_0402_16V7K~D  [C_0402]  254.18 52.53 270 top
CD130  0.022U_0402_25V7K  [C_0402]  220.73 71.03 180 top
CD131  .1U_0402_16V7K  [C_0402]  227.53 72.85 270 top
CD132  .1U_0402_16V7K  [C_0402]  225.83 71.02 90 top
CD133  0.1U_0402_16V7K~D  [C_0402]  212.55 52.27 90 top
CD134  0.1U_0402_16V7K~D  [C_0402]  242.62 53.52 0 top
CE1  .1U_0402_16V7K  [C_0402]  352.33 31.82 90 top
CE2  15P_0402_50V  [C_0402]  360.67 42.89 0 bottom
CE5  15P_0402_50V  [C_0402]  359.83 42.89 180 bottom
CE6  .1U_0402_16V7K  [C_0402]  364.67 38.53 90 top
CE7  1U_0201_6.3V6M  [C_0201]  365.4 27.48 0 top
CE8  0.1U_0402_16V7K  [C_0402]  358.14 41.5 180 top
CE9  1U_0201_6.3V6M  [C_0201]  365.4 28.06 0 top
CE19  .1U_0402_16V7K  [C_0402]  367.13 41.55 90 top
CE22  4.7U_0603_10V  [C_0603]  352.12 26.35 270 top
CE24  .1U_0402_16V7K  [C_0402]  156.16 181.43 90 top
CE28  0.1U_0402_10V7K  [C_0402]  309.96 7.92 0 top
CE29  0.1U_0402_10V7K  [C_0402]  287.74 22.81 90 top
CE30  0.1U_0402_10V7K  [C_0402]  309.57 24.86 0 top
CE31  1000P_0402_50V7K  [C_0402]  287.96 15.49 0 top
CE32  1000P_0402_50V7K  [C_0402]  292.76 7.95 180 top
CE34  .047U_0402_16V7K  [C_0402]  288.11 19.05 180 top
CE35  100P_0402_50V8J  [C_0402]  305.49 6.35 90 top
CE38  0.1U_0402_10V7K  [C_0402]  295.25 28.57 270 top
CE40  100P_0402_50V8J  [C_0402]  301.53 28.7 270 top
CE41  0.1U_0402_10V7K  [C_0402]  285.89 23.58 0 top
CE42  0.1U_0402_10V7K  [C_0402]  310.49 23.95 180 top
CE43  0.1U_0402_10V7K  [C_0402]  298.27 30.5 0 top
CE44  0.1U_0402_10V7K  [C_0402]  289.56 10.97 90 top
CE45  0.1U_0402_10V7K  [C_0402]  288.72 18.18 270 top
CE46  0.1U_0402_10V7K  [C_0402]  310.18 15.01 0 top
CE51  0.033U_0402_25V  [C_0402]  303.02 29.46 90 top
CE59  .1U_0402_16V7K  [C_0402]  362.66 27.66 270 top
CE60  .1U_0402_16V7K  [C_0402]  362.28 41.25 90 top
CE61  .1U_0402_16V7K  [C_0402]  107.6 125.49 90 bottom
CE62  .1U_0402_16V7K  [C_0402]  247.8 5.89 270 top
CE63  0.1U_0402_16V7K~D  [C_0402]  250.55 8.96 180 top
CE64  0.1U_0402_16V7K  [C_0402]  351.28 31.29 90 top
CE65  10U_0402_6.3V6M  [C_0402]  350.37 31.29 90 top
CE79  0.1U_0402_10V6K  [C_0402]  303.06 47.14 180 bottom
CE80  4.7U_0805_10V4Z  [C_0805]  303.2 41.48 180 bottom
CE81  0.1U_0402_10V6K  [C_0402]  301.07 46.19 0 bottom
CE82  0.1U_0402_10V6K  [C_0402]  299.13 46.15 180 bottom
CE86  .1U_0402_16V7K  [C_0402]  159.29 177.94 90 top
CE87  .1U_0402_16V7K  [C_0402]  233.56 106.13 180 bottom
CE169  .1U_0402_16V7K  [C_0402]  365.4 26.67 0 top
CE170  1U_0201_6.3V6M  [C_0201]  361.9 27.44 270 top
CE171  0.1U_0402_10V7K  [C_0402]  297.91 27.76 90 top
CE172  0.1U_0402_10V7K  [C_0402]  310.01 8.79 90 top
CE173  12P_0402_50V8J  [C_0402]  350.16 35.3 180 top
CE174  0.1U_0402_16V7K  [C_0402]  288.77 20.72 180 top
CE175  .1U_0402_16V7K  [C_0402]  250.59 106.82 0 bottom
CE176  .1U_0402_16V7K  [C_0402]  233.56 107.08 180 bottom
CE177  1U_0201_6.3V6M  [C_0201]  361.32 27.44 270 top
CE201  .1U_0402_16V7K  [C_0402]  283.13 5.1 180 top
CE202  0.1U_0402_16V7K~D  [C_0402]  286.64 8.28 180 top
CE203  22U_0603_6.3V6M  [C_0603]  271.25 80.43 90 top
CE204  4.7U_0805_10V4Z  [C_0805]  266.13 80.36 90 top
CE205  0.1U_0402_16V7K  [C_0402]  267.36 84.66 0 top
CF4  22U_0603_6.3V6M  [C_0603]  91.55 52.75 0 bottom
CF5  22U_0805_6.3VAM  [C_0805]  373.56 48.88 270 bottom
CF6  22U_0805_25V6M  [C_0805]  87.71 54.6 270 bottom
CF7  22U_0805_25V6M  [C_0805]  371.68 48.88 270 bottom
CH36  4.7U_0402_6.3V6M  [C_0402]  294.39 67.38 45 top
CH45  10P_0402_50V8J  [C_0402]  263.6 64.82 270 top
CH46  10P_0402_50V8J  [C_0402]  263.6 65.66 90 top
CH47  15P_0402_50V  [C_0402]  296.58 48.35 270 bottom
CH48  15P_0402_50V  [C_0402]  296.61 49.2 90 bottom
CH49  0.1U_0402_16V7K  [C_0402]  262.3 102.32 0 bottom
CH52  1U_0603_10V6K~D  [C_0603]  259.75 64.74 180 top
CH53  1U_0603_10V6K~D  [C_0603]  281.96 82.51 270 bottom
CH56  47U_0805_6.3V6M  [C_0805]  300.41 45.81 180 top
CH80  1U_0201_6.3V6M  [C_0201]  265.26 69.92 180 top
CH81  1U_0201_6.3V6M  [C_0201]  265.26 70.48 180 top
CH82  1U_0201_6.3V6M  [C_0201]  296.55 38.26 180 top
CH83  1U_0201_6.3V6M  [C_0201]  295.38 38.86 270 top
CH173  0.1U_0402_10V7K  [C_0402]  265.3 69.19 180 top
CH174  0.1U_0402_10V  [C_0402]  272.16 74.45 90 top
CH175  0.1U_0402_10V  [C_0402]  296.77 65.12 180 top
CH176  1U_0201_6.3V6M  [C_0201]  283.82 54.75 0 bottom
CH177  1U_0201_6.3V6M  [C_0201]  283.82 54.18 0 bottom
CH180  1U_0201_6.3V6M  [C_0201]  280.56 47.91 0 bottom
CH181  22U_0603_6.3V6M  [C_0603]  280.89 44.24 0 bottom
CH182  1U_0603_10V6K  [C_0603]  291.91 67.82 0 bottom
CH183  1U_0201_6.3V6M  [C_0201]  280.56 47.33 0 bottom
CH184  1U_0201_6.3V6M  [C_0201]  265.29 41.62 180 top
CH185  1U_0201_6.3V6M  [C_0201]  264.64 52.77 180 top
CH186  0.1U_0402_10V7K  [C_0402]  267.31 71.19 0 top
CH187  1U_0201_6.3V6M  [C_0201]  265.29 42.19 180 top
CH188  1U_0201_6.3V6M  [C_0201]  264.64 52.19 180 top
CH189  22U_0603_6.3V6M  [C_0603]  280.89 45.46 0 bottom
CH190  0.1U_0402_10V7K  [C_0402]  264.56 53.5 180 top
CH192  0.1U_0402_10V7K  [C_0402]  266.37 71.24 180 top
CH197  0.1U_0402_10V7K  [C_0402]  176.05 29.25 270 top
CH201  0.1U_0201_6.3V6K  [C_0201]  282.28 78.85 90 bottom
CH202  0.22U_0201_6.3V  [C_0201]  276.22 37.58 90 top
CH203  0.22U_0201_6.3V  [C_0201]  276.81 37.58 90 top
CH204  0.22U_0201_6.3V  [C_0201]  275.39 36.33 90 top
CH205  0.22U_0201_6.3V  [C_0201]  275.97 36.33 90 top
CH206  0.22U_0201_6.3V  [C_0201]  275.01 38.14 270 top
CH207  0.22U_0201_6.3V  [C_0201]  274.42 38.14 270 top
CH208  0.22U_0201_6.3V  [C_0201]  274.17 36.89 270 top
CH209  0.22U_0201_6.3V  [C_0201]  273.58 36.89 270 top
CH210  0.22U_0201_6.3V  [C_0201]  271.42 37.5 90 top
CH211  0.22U_0201_6.3V  [C_0201]  270.84 37.5 90 top
CH212  0.22U_0201_6.3V  [C_0201]  271.8 36.31 90 top
CH213  0.22U_0201_6.3V  [C_0201]  272.39 36.31 90 top
CH214  0.22U_0201_6.3V  [C_0201]  269.95 36.87 270 top
CH215  0.22U_0201_6.3V  [C_0201]  270.53 36.87 270 top
CH216  0.22U_0201_6.3V  [C_0201]  269.47 38.14 270 top
CH217  0.22U_0201_6.3V  [C_0201]  268.91 38.15 270 top
CH226  0.1U_0402_10V7K  [C_0402]  265.33 68.27 180 top
CH227  0.01U_0201_16V7  [C_0201]  273.3 37.53 90 top
CH228  0.01U_0201_16V7  [C_0201]  272.72 37.53 90 top
CH229  0.01U_0201_16V7  [C_0201]  267.74 36.36 90 top
CH230  0.01U_0201_16V7  [C_0201]  268.33 36.36 90 top
CH231  0.5P_0402_50V8  [C_0402]  264.62 51.43 180 top
CH232  33P_0402_50V8J  [C_0402]  262.95 109.84 0 bottom
CH233  4.7U_0603_6.3V6M  [C_0603]  287.16 63.37 180 bottom
CH234  0.5P_0402_50V8  [C_0402]  210.77 53.16 0 top
CH235  10P_0402_50V8J  [C_0402]  211.56 64.41 180 top
CH236  0.5P_0402_50V8  [C_0402]  226.19 52.45 0 top
CH237  10P_0402_50V8J  [C_0402]  217.93 66.27 0 top
CH238  0.5P_0402_50V8  [C_0402]  233.25 63.08 0 top
CH239  10P_0402_50V8J  [C_0402]  238.89 67.41 0 top
CH240  0.5P_0402_50V8  [C_0402]  254.13 54.56 90 top
CH241  10P_0402_50V8J  [C_0402]  255.88 65.35 0 top
CH242  10P_0402_50V8J  [C_0402]  36.47 38.22 0 bottom
CH243  10P_0402_50V8J  [C_0402]  291.02 68.25 135 top
CH244  10P_0402_50V8J  [C_0402]  274.65 75.26 0 top
CH245  0.1U_0402_10V7K  [C_0402]  263.7 50.52 0 top
CH246  22P_0402_50V8J  [C_0402]  261.45 58.84 270 top
CH247  0.22U_0201_6.3V  [C_0201]  51.55 29.23 180 top
CH248  0.22U_0201_6.3V  [C_0201]  51.55 29.79 180 top
CH249  0.22U_0201_6.3V  [C_0201]  51.55 24.25 180 top
CH250  0.22U_0201_6.3V  [C_0201]  51.55 24.81 180 top
CH251  0.22U_0201_6.3V  [C_0201]  51.55 28.12 180 top
CH252  0.22U_0201_6.3V  [C_0201]  51.55 28.67 180 top
CH253  0.22U_0201_6.3V  [C_0201]  51.55 23.14 180 top
CH254  0.22U_0201_6.3V  [C_0201]  51.55 23.7 180 top
CH255  0.22U_0201_6.3V  [C_0201]  51.57 26.74 180 top
CH256  0.22U_0201_6.3V  [C_0201]  51.57 27.3 180 top
CH257  0.22U_0201_6.3V  [C_0201]  51.55 22.02 180 top
CH258  0.22U_0201_6.3V  [C_0201]  51.55 22.58 180 top
CH259  0.22U_0201_6.3V  [C_0201]  51.57 25.63 180 top
CH260  0.22U_0201_6.3V  [C_0201]  51.57 26.19 180 top
CH261  0.22U_0201_6.3V  [C_0201]  51.52 20.9 180 top
CH262  0.22U_0201_6.3V  [C_0201]  51.55 21.46 180 top
CH263  47U_0805_6.3V6M  [C_0805]  265.05 37.49 0 top
CH264  0.1U_0402_10V7K  [C_0402]  269.27 68.3 270 top
CI38  0.1U_0402_10V6K  [C_0402]  166.1 186.99 90 top
CI39  0.1U_0402_10V6K  [C_0402]  165.16 186.99 90 top
CL1  0.1U_0402_16V7K~D  [C_0402]  180.3 176.54 90 top
CL2  0.1U_0402_16V7K~D  [C_0402]  177.19 174.45 90 top
CL3  33P_0201_25V8J  [C_0201]  184.07 160.75 0 bottom
CL4  33P_0201_25V8J  [C_0201]  183.45 160.75 180 bottom
CL5  0.1U_0402_16V7K  [C_0402]  176.69 168.49 180 top
CL6  0.1U_0402_16V7K  [C_0402]  176.69 169.38 180 top
CL7  0.1U_0402_16V7K  [C_0402]  176.69 167.22 180 top
CL8  0.1U_0402_16V7K  [C_0402]  176.69 166.33 180 top
CL9  0.1U_0402_16V7K~D  [C_0402]  201.14 163.88 90 bottom
CL10  10P_1808_3KV7K~D  [C_1808]  190.91 178.13 0 top
CL20  22U_0603_6.3V6M  [C_0603]  192.56 165 180 top
CL21  100P_0402_50V8J  [C_0402]  194.61 166.74 180 bottom
CL22  22U_0402_6.3V6M  [C_0402]  196.71 163.88 90 bottom
CL23  22U_0402_6.3V6M  [C_0402]  195.1 163.08 90 bottom
CL24  22U_0603_6.3V6M  [C_0603]  173.26 161.76 270 top
CL25  100P_0402_50V8J  [C_0402]  174.59 170.53 270 bottom
CL26  22U_0402_6.3V6M  [C_0402]  175.23 171.97 90 bottom
CL27  22U_0402_6.3V6M  [C_0402]  174.33 171.97 90 bottom
CL28  2200P_0402_25V7K  [C_0402]  189.46 162.04 180 top
CL29  6800P_0402_25V7K  [C_0402]  189.46 161.12 180 top
CL31  470P_0402_50V7K  [C_0402]  213.05 169.01 270 bottom
CL40  10U_0603_6.3V6M~D  [C_0603]  190.84 169.95 90 bottom
CL41  10U_0603_6.3V6M~D  [C_0603]  190.84 165.76 90 bottom
CL42  10U_0603_6.3V6M~D  [C_0603]  186.52 161.95 270 top
CL43  10U_0603_6.3V6M~D  [C_0603]  186.91 176.17 90 top
CL44  10U_0603_6.3V6M~D  [C_0603]  190.72 172.93 0 top
CL45  0.1U_0402_16V7K~D  [C_0402]  181.07 162.15 270 top
CL46  0.1U_0402_16V7K~D  [C_0402]  183.6 174.47 270 bottom
CL47  10U_0603_6.3V6M~D  [C_0603]  186.84 176.17 90 bottom
CL48  10U_0603_6.3V6M~D  [C_0603]  188.18 170.27 180 bottom
CL49  10U_0603_6.3V6M~D  [C_0603]  188.87 169.06 180 bottom
CL50  10U_0603_6.3V6M~D  [C_0603]  187.04 161.88 0 bottom
CL51  10U_0603_6.3V6M~D  [C_0603]  186.66 164.17 90 bottom
CL52  0.1U_0402_16V7K~D  [C_0402]  177.33 163.54 180 top
CL53  10U_0603_6.3V6M~D  [C_0603]  177.1 162.52 270 top
CL54  10U_0603_6.3V6M~D  [C_0603]  188.24 173.95 180 bottom
CL55  10U_0603_6.3V6M~D  [C_0603]  188.18 172.74 180 bottom
CL56  10U_0603_6.3V6M~D  [C_0603]  188.87 166.65 180 bottom
CL57  10U_0603_6.3V6M~D  [C_0603]  188.68 165.57 270 bottom
CL58  10U_0603_6.3V6M~D  [C_0603]  185.2 165.06 90 bottom
CL59  0.1U_0402_16V7K~D  [C_0402]  178.57 170.46 0 bottom
CL60  0.1U_0402_16V7K~D  [C_0402]  182.71 174.47 270 bottom
CL61  0.1U_0402_16V7K~D  [C_0402]  180.75 164.16 90 bottom
CL62  0.1U_0402_16V7K~D  [C_0402]  176.62 170.44 90 top
CL63  10U_0603_6.3V6M~D  [C_0603]  175.54 170.52 90 top
CL64  0.1U_0402_16V7K~D  [C_0402]  176.68 165.39 270 top
CL65  10U_0603_6.3V6M~D  [C_0603]  175.28 165.31 270 top
CL66  10U_0603_6.3V6M~D  [C_0603]  188.05 176.17 90 bottom
CL67  10U_0603_6.3V6M~D  [C_0603]  188.94 171.47 180 bottom
CL68  10U_0603_6.3V6M~D  [C_0603]  188.18 167.85 180 bottom
CL69  10U_0603_6.3V6M~D  [C_0603]  190.02 163.79 270 bottom
CL70  10U_0603_6.3V6M~D  [C_0603]  183.8 165.19 90 bottom
CL71  2.2U_0402_6.3V6M  [C_0402]  182.65 165.07 270 bottom
CL72  2.2U_0402_6.3V6M  [C_0402]  181.76 165.07 270 bottom
CL73  2.2U_0402_6.3V6M  [C_0402]  179.6 173.62 90 bottom
CL74  2.2U_0402_6.3V6M  [C_0402]  184.49 173.56 90 bottom
CL75  2.2U_0402_6.3V6M  [C_0402]  179.49 171.35 180 bottom
CL76  2.2U_0402_6.3V6M  [C_0402]  179.49 172.24 180 bottom
CL77  0.1U_0402_16V7K~D  [C_0402]  178.64 166.24 0 bottom
CL78  0.1U_0402_16V7K~D  [C_0402]  178.57 169.57 0 bottom
CL79  0.1U_0402_16V7K~D  [C_0402]  178.57 168.68 0 bottom
CL80  10U_0603_6.3V6M~D  [C_0603]  178.64 167.32 0 bottom
CL81  10U_0603_6.3V6M~D  [C_0603]  176.19 166.13 315 bottom
CL82  10U_0603_6.3V6M~D  [C_0603]  175.3 165.24 315 bottom
CL90  1U_0402_6.3V6K~D  [C_0402]  190.21 165.01 270 top
CL91  1U_0201_6.3V6M  [C_0201]  190.85 166.69 0 top
CL92  1U_0201_6.3V6M  [C_0201]  190.85 169.26 0 top
CL93  1U_0201_6.3V6M  [C_0201]  190.86 169.84 0 top
CL94  1U_0201_6.3V6M  [C_0201]  190.86 172.04 0 top
CL95  1U_0201_6.3V6M  [C_0201]  189.55 176.15 90 top
CL96  1U_0201_6.3V6M  [C_0201]  187.81 177.3 0 top
CL97  1U_0201_6.3V6M  [C_0201]  182.37 162.05 270 top
CL98  1U_0402_6.3V6K~D  [C_0402]  187.67 162.22 270 top
CL99  1U_0201_6.3V6M  [C_0201]  178.73 165.5 0 bottom
CL100  0.1U_0402_10V6K  [C_0402]  169.76 174.57 90 top
CL101  100P_0402_50V8J  [C_0402]  163.81 165.63 180 top
CL102  22U_0402_6.3V6M  [C_0402]  165.12 164.79 90 top
CL103  22U_0603_6.3V6M  [C_0603]  160.17 163.03 270 top
CL104  22U_0402_6.3V6M  [C_0402]  166.01 164.79 90 top
CL107  470P_0402_50V7K  [C_0402]  192.48 183.77 180 bottom
CL108  470P_0402_50V7K  [C_0402]  213.96 169.01 270 bottom
CL109  470P_0402_50V7K  [C_0402]  212.24 166.79 270 bottom
CL110  0.1U_0402_16V7K~D  [C_0402]  198.15 163.88 90 bottom
CL111  0.1U_0402_16V7K~D  [C_0402]  199.04 163.88 90 bottom
CL112  0.1U_0402_16V7K~D  [C_0402]  203.84 163.85 90 bottom
CL113  1000P_0402_50V7K  [C_0402]  202.07 163.85 90 bottom
CL114  1000P_0402_50V7K  [C_0402]  202.95 163.85 90 bottom
CL115  1000P_0402_50V7K  [C_0402]  204.73 163.85 90 bottom
CL116  1000P_0402_50V7K  [C_0402]  199.93 163.88 90 bottom
CL117  0.1U_0402_16V7K  [C_0402]  162.94 167.56 180 top
CL118  4.7U_0805_10V4Z  [C_0805]  162.85 168.88 180 top
CL119  0.1U_0402_16V7K  [C_0402]  162.99 170.25 180 top
CL120  22U_0603_6.3V6M  [C_0603]  167.67 167.41 90 top
CL121  1U_0201_6.3V6M  [C_0201]  190.85 167.26 0 top
CL122  1U_0201_6.3V6M  [C_0201]  190.85 168.68 0 top
CL123  1U_0201_6.3V6M  [C_0201]  190.86 170.41 0 top
CL124  1U_0201_6.3V6M  [C_0201]  190.86 171.47 0 top
CL125  1U_0201_6.3V6M  [C_0201]  188.79 176.15 180 top
CL126  1U_0201_6.3V6M  [C_0201]  187.81 176.74 0 top
CL127  1U_0201_6.3V6M  [C_0201]  181.8 162.05 270 top
CL129  1U_0201_6.3V6M  [C_0201]  178.73 164.93 0 bottom
CLIP1  -  [CLIP_10P2X7P2_SHIELDING_CASE1]  27.91 26.38 270 bottom
CLIP2  -  [EMIST_SQ-42G-2_1P]  265.9 120.8 180 bottom
CLRP1  SHORT PADS  [SHORTPADS]  283.23 81.63 270 bottom
CM9  0.1U_0402_10V7K  [C_0402]  177.37 180.45 0 bottom
CM16  0.1U_0402_10V7K  [C_0402]  165.66 176.45 0 bottom
CM17  0.1U_0402_10V7K  [C_0402]  165.66 175.54 0 bottom
CM18  0.1U_0402_10V7K  [C_0402]  159.49 168.48 270 bottom
CM19  22U_0603_6.3V6M  [C_0603]  166.27 173.72 270 bottom
CM20  0.1U_0402_10V7K  [C_0402]  162.05 168.48 270 bottom
CM21  1U_0201_6.3V6M  [C_0201]  162.02 177.1 180 bottom
CM22  1U_0201_6.3V6M  [C_0201]  162.02 177.67 180 bottom
CM23  0.1U_0402_10V7K  [C_0402]  168.3 194.54 180 bottom
CM29  10U_0603_6.3V6M  [C_0603]  162.24 183.82 180 bottom
CM30  1U_0201_6.3V6M  [C_0201]  163.14 181.53 270 bottom
CM31  10U_0603_6.3V6M  [C_0603]  162.27 182.57 180 bottom
CM32  0.1U_0402_10V7K  [C_0402]  170.61 185.19 90 bottom
CM33  1U_0201_6.3V6M  [C_0201]  164.29 181.54 270 bottom
CM34  0.1U_0402_10V7K  [C_0402]  173.13 185.16 90 bottom
CM35  0.1U_0402_10V7K  [C_0402]  169.76 175.49 270 bottom
CM36  0.1U_0402_10V7K  [C_0402]  168.5 175.87 270 bottom
CM37  1U_0201_6.3V6M  [C_0201]  162.56 181.52 270 bottom
CM38  1U_0201_6.3V6M  [C_0201]  163.72 181.53 270 bottom
CM62  0.22U_0201_6.3V  [C_0201]  172.54 175.4 90 bottom
CM63  0.22U_0201_6.3V  [C_0201]  171.96 175.4 90 bottom
CM64  0.22U_0201_6.3V  [C_0201]  175.46 175.42 90 bottom
CM65  0.22U_0201_6.3V  [C_0201]  174.88 175.42 90 bottom
CM66  0.22U_0201_6.3V  [C_0201]  171.37 175.4 90 bottom
CM67  0.22U_0201_6.3V  [C_0201]  174.29 175.42 90 bottom
CM68  0.22U_0201_6.3V  [C_0201]  173.13 175.4 90 bottom
CM69  0.22U_0201_6.3V  [C_0201]  173.71 175.42 90 bottom
CM70  0.1U_0402_10V7K  [C_0402]  185.66 186.84 90 top
CM98  0.01U_0402_16V7K  [C_0402]  160.71 180.38 90 bottom
CM99  0.01U_0402_16V7K  [C_0402]  159.79 180.38 90 bottom
CN1  0.1U_0402_10V7K  [C_0402]  334.85 35.56 90 top
CN2  4.7U_0805_10V4Z  [C_0805]  335.29 33.75 180 top
CN3  22U_0603_6.3V6M~D  [C_0603]  337.78 34.64 0 top
CN4  0.1U_0402_10V7K~D  [C_0402]  337.69 33.58 0 top
CN5  10P_0402_50V8J  [C_0402]  335.74 35.56 90 top
CN6  0.1U_0402_16V7K  [C_0402]  346.05 41.04 0 bottom
CN7  0.1U_0402_16V7K  [C_0402]  346.05 41.93 0 bottom
CN8  22U_0603_6.3V6M~D  [C_0603]  340.59 48.27 90 top
CN9  0.1U_0402_10V7K~D  [C_0402]  339.55 48.84 90 top
CS1  10U_0603_25V6M  [C_0603]  252.22 9.54 90 top
CS2  10U_0603_6.3V6M  [C_0603]  220.71 18.77 180 bottom
CS5  1000P_0402_50V7K~D  [C_0402]  252.22 7.14 270 top
CS6  0.1U_0402_25V6K~D  [C_0402]  253.16 7.11 270 top
CS7  .1U_0402_16V7K  [C_0402]  220.57 16.94 270 bottom
CS16  22U_0402_6.3V6M  [C_0402]  254.08 7.11 270 top
CS17  .1U_0402_16V7K  [C_0402]  112.18 169.82 180 top
CS18  .1U_0402_16V7K  [C_0402]  114.02 169.82 180 top
CS19  .1U_0402_16V7K  [C_0402]  279.37 79.7 0 top
CS20  .1U_0402_16V7K  [C_0402]  279.4 80.62 0 top
CT1  0.22U_0201_6.3V  [C_0201]  28.12 35.21 90 bottom
CT2  0.22U_0201_6.3V  [C_0201]  26.22 35.21 90 bottom
CT3  0.22U_0201_6.3V  [C_0201]  30.03 35.21 90 bottom
CT4  0.22U_0201_6.3V  [C_0201]  25.58 35.21 90 bottom
CT5  0.22U_0201_6.3V  [C_0201]  23.04 35.21 90 bottom
CT6  0.1U_0201_6.3V6K  [C_0201]  32.44 45.54 180 bottom
CT7  0.1U_0201_6.3V6K  [C_0201]  32.44 44.9 180 bottom
CT8  0.1U_0201_6.3V6K  [C_0201]  33.71 43.96 180 bottom
CT9  0.1U_0201_6.3V6K  [C_0201]  33.71 44.7 180 bottom
CT10  0.1U_0201_6.3V6K  [C_0201]  32.44 43.07 180 bottom
CT11  0.1U_0201_6.3V6K  [C_0201]  33.71 42.36 180 bottom
CT12  0.22U_0201_6.3V  [C_0201]  26.85 35.21 90 bottom
CT13  0.22U_0201_6.3V  [C_0201]  27.49 35.21 90 bottom
CT14  0.22U_0201_6.3V  [C_0201]  29.39 35.21 90 bottom
CT15  0.22U_0201_6.3V  [C_0201]  30.66 35.21 90 bottom
CT16  0.22U_0201_6.3V  [C_0201]  28.76 35.21 90 bottom
CT18  0.22U_0201_6.3V  [C_0201]  24.95 35.21 90 bottom
CT21  0.22U_0201_6.3V  [C_0201]  22.41 35.21 90 bottom
CT23  0.1U_0201_6.3V6K  [C_0201]  32.44 43.81 180 bottom
CT24  0.1U_0201_6.3V6K  [C_0201]  33.71 43 180 bottom
CT25  0.1U_0201_6.3V6K  [C_0201]  34.19 43.1 180 top
CT26  0.1U_0201_6.3V6K  [C_0201]  34.19 43.68 180 top
CT27  0.1U_0201_6.3V6K  [C_0201]  32.44 41.98 180 bottom
CT28  0.1U_0201_6.3V6K  [C_0201]  32.44 41.35 180 bottom
CT29  0.1U_0201_6.3V6K  [C_0201]  33.71 41.09 180 bottom
CT30  0.1U_0201_6.3V6K  [C_0201]  33.71 40.46 180 bottom
CT31  0.1U_0201_6.3V6K  [C_0201]  32.44 40.08 180 bottom
CT32  0.1U_0201_6.3V6K  [C_0201]  32.44 39.44 180 bottom
CT33  0.1U_0201_6.3V6K  [C_0201]  32.44 38.81 180 bottom
CT34  0.1U_0201_6.3V6K  [C_0201]  32.44 38.17 180 bottom
CT35  0.1U_0201_6.3V6K  [C_0201]  33.61 41.93 180 top
CT36  0.1U_0201_6.3V6K  [C_0201]  33.61 41.37 180 top
CT37  27P_0201_25V  [C_0201]  25.5 26.85 0 bottom
CT38  27P_0201_25V  [C_0201]  24.82 26.85 180 bottom
CT39  0.22U_0201_6.3V  [C_0201]  17.01 40.91 0 bottom
CT40  0.22U_0201_6.3V  [C_0201]  17.01 40.33 0 bottom
CT41  0.22U_0201_6.3V  [C_0201]  16.97 39.05 0 bottom
CT42  0.22U_0201_6.3V  [C_0201]  16.97 39.6 0 bottom
CT43  0.1U_0201_6.3V6K  [C_0201]  32.45 39.44 180 top
CT44  0.1U_0201_6.3V6K  [C_0201]  32.45 40.08 180 top
CT45  0.1U_0201_6.3V6K  [C_0201]  46.09 32.08 0 bottom
CT46  0.1U_0201_6.3V6K  [C_0201]  26.74 45.16 0 top
CT47  1U_0201_6.3V6M  [C_0201]  21.36 45.7 180 top
CT48  1U_0201_6.3V6M  [C_0201]  22.63 44.43 0 top
CT49  1U_0201_6.3V6M  [C_0201]  17.76 47.91 90 bottom
CT50  10U_0402_6.3V6M  [C_0402]  16.34 51.71 0 bottom
CT51  10U_0402_6.3V6M  [C_0402]  16.34 50.82 0 bottom
CT52  10U_0402_6.3V6M  [C_0402]  16.34 49.81 0 bottom
CT53  10U_0402_6.3V6M  [C_0402]  16.34 52.6 0 bottom
CT54  1U_0201_6.3V6M  [C_0201]  23.43 42.67 0 top
CT55  1U_0201_6.3V6M  [C_0201]  24.97 40.15 90 top
CT56  1U_0201_6.3V6M  [C_0201]  26.71 40.72 0 top
CT57  1U_0201_6.3V6M  [C_0201]  25 46.22 90 top
CT58  1U_0201_6.3V6M  [C_0201]  24.87 45.05 90 top
CT59  1U_0201_6.3V6M  [C_0201]  24.41 44.43 180 top
CT60  1U_0201_6.3V6M  [C_0201]  26.22 42.46 180 top
CT61  1U_0201_6.3V6M  [C_0201]  27.41 42.45 180 top
CT62  1U_0201_6.3V6M  [C_0201]  28.02 42.19 0 top
CT63  1U_0201_6.3V6M  [C_0201]  21.11 42.69 90 top
CT64  1U_0201_6.3V6M  [C_0201]  19.99 44.7 180 top
CT65  1U_0201_6.3V6M  [C_0201]  19.75 44.09 180 top
CT66  1U_0201_6.3V6M  [C_0201]  20.1 42.35 180 top
CT67  1U_0201_6.3V6M  [C_0201]  20.1 42.91 180 top
CT68  1U_0201_6.3V6M  [C_0201]  19.75 43.53 180 top
CT69  1U_0201_6.3V6M  [C_0201]  19.85 41.79 0 top
CT70  1U_0201_6.3V6M  [C_0201]  24.82 41.93 90 top
CT71  1U_0201_6.3V6M  [C_0201]  25.28 38.78 270 top
CT72  1U_0201_6.3V6M  [C_0201]  24.72 38.78 270 top
CT73  47U_0603_6.3V6M  [C_0603]  19.53 50.21 180 bottom
CT74  47U_0603_6.3V6M  [C_0603]  19.53 51.42 180 bottom
CT75  47U_0603_6.3V6M  [C_0603]  19.53 52.62 180 bottom
CT77  1U_0201_6.3V6M  [C_0201]  25.61 41.32 180 top
CT78  1U_0201_6.3V6M  [C_0201]  26.11 43.21 90 top
